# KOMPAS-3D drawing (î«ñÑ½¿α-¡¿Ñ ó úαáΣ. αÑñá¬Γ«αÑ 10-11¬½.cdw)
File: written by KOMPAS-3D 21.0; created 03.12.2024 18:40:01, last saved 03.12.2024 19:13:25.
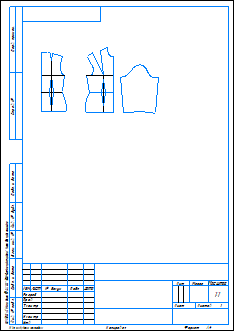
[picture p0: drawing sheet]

Sheet 1: A4, portrait

Document properties: Автор: Admin; Полное имя файла: C:\Users\Admin\Desktop\77\10-11 класс.cdw

Title block, sheet 1: scale: 1:1; Количество листов документа: 1; Форматы листов документа: A4

Dimensions and other numbers on the sheet: 1:1; 1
